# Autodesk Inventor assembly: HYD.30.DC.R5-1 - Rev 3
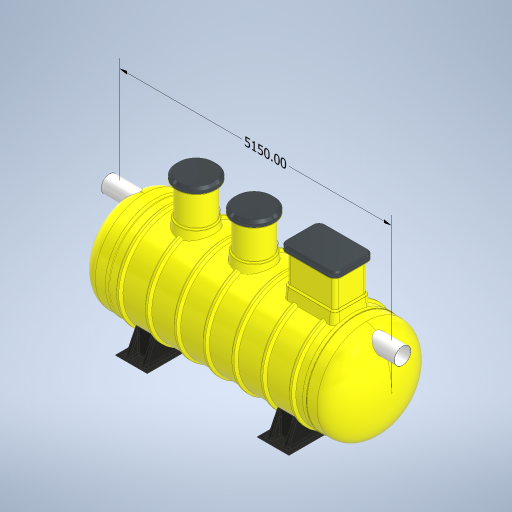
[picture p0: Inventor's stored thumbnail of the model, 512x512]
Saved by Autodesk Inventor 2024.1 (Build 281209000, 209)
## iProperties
Created: 2023-08
Part Number: HYD.30.DC.R5-1 - Rev 3
Document SubType Name: Assembly
Designer: macga
Author: macga
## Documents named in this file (43)
- D:\$ Protector Vault\Workspace\Automation Files\1. Protector Stardard Products\HydroProtectors\FAMILY\HYD.30 - Vernon\HYD.30.DC.R5-1 - Rev 3.iam
- D:\$ Protector Vault\Workspace\1. Protector Stardard Products\HydroProtectors\FAMILY\HORIZONTAL TANK - IPART\HORIZONTAL TANK - IPART.ipt
- D:\$ Protector Vault\Workspace\1. Protector Stardard Products\HydroProtectors\FAMILY\DOME - IPART\DOME - IPART\SU.DOME.1850-9.ipt
- D:\$ Protector Vault\Workspace\1. Protector Stardard Products\HydroProtectors\FAMILY\DOME - IPART\DOME - IPART.ipt
- D:\$ Protector Vault\Workspace\1. Protector Stardard Products\HydroProtectors\FAMILY\FOOT - IPART\FRP Foot - IPART\SU.HS.FOOT.1850.ipt
- D:\$ Protector Vault\Workspace\1. Protector Stardard Products\HydroProtectors\FAMILY\FOOT - IPART\FRP Foot - IPART.ipt
- D:\$ Protector Vault\Workspace\1. Protector Stardard Products\HydroProtectors\FAMILY\HYD.BAFFLE - IPART\SU.BAFFLE.1850\SU.BAFFLE.1850.ipt
- D:\$ Protector Vault\Workspace\1. Protector Stardard Products\HydroProtectors\FAMILY\HYD.BAFFLE - IPART\SU.BAFFLE.1850.ipt
- D:\$ Protector Vault\Workspace\1. Protector Stardard Products\HydroProtectors\FAMILY\ACD Base - IPART\SU.ACDBASE.1850\SU.ACDBASE.1850-300ACDFV.ipt
- D:\$ Protector Vault\Workspace\1. Protector Stardard Products\HydroProtectors\FAMILY\ACD Base - IPART\SU.ACDBASE.1850.ipt
- D:\$ Protector Vault\Workspace\1. Protector Stardard Products\HydroProtectors\FAMILY\ACDTUBE - IPART\ACDTUBE - IPART\ACDTUBE.300-1880.ipt
- D:\$ Protector Vault\Workspace\1. Protector Stardard Products\HydroProtectors\FAMILY\ACDTUBE - IPART\ACDTUBE - IPART.ipt
- D:\$ Protector Vault\Workspace\1. Protector Stardard Products\HydroProtectors\FAMILY\ACD FLOAT VALVE - IPART\ACD.FloatValve - IASSY\ACD.FVALVE.300.ASSY.iam
- D:\$ Protector Vault\Workspace\1. Protector Stardard Products\HydroProtectors\FAMILY\ACD FLOAT VALVE - IPART\ACD.FloatValve - IASSY.iam
- D:\$ Protector Vault\Workspace\1. Protector Stardard Products\HydroProtectors\FAMILY\SU.600Dia Manway Adaptor - IPART\Horizontal 600mmDia Manway Adaptor (FLANGED) SU.MWA.HS.6R-1850-1850\SU.MWA.HS.6R-1850.ipt
- D:\$ Protector Vault\Workspace\1. Protector Stardard Products\HydroProtectors\FAMILY\SU.600Dia Manway Adaptor - IPART\SU.MWA.HS.6R - IPART.ipt
- D:\$ Protector Vault\Workspace\1. Protector Stardard Products\HydroProtectors\FAMILY\WIN.600mmDiaManwayRiser - IPART\600mmDia Manway Riser.ipt
- D:\$ Protector Vault\Workspace\1. Protector Stardard Products\HydroProtectors\Automation Files\600mmDia Manway Cover.ipt
- D:\$ Protector Vault\Workspace\1. Protector Stardard Products\HydroProtectors\HYD.50 300 Outlet Vertical.ipt
- D:\$ Protector Vault\Workspace\1. Protector Stardard Products\HydroProtectors\FAMILY\OUTLET ELBOW - IPART\OUTLET ELBOW - IPART.ipt
- D:\$ Protector Vault\Workspace\1. Protector Stardard Products\HydroProtectors\Coalescer Guide Rail.ipt
- D:\$ Protector Vault\Workspace\1. Protector Stardard Products\HydroProtectors\ISO 4065 Pipe DN315x2.5xS63 - 1365.ipt
- D:\$ Protector Vault\Workspace\1. Protector Stardard Products\HydroProtectors\FAMILY\INLET PIPE ELBOW- IPART\INLET PIPE ELBOW- IPART\InletPipeElbow.300D.ipt
- D:\$ Protector Vault\Workspace\1. Protector Stardard Products\HydroProtectors\FAMILY\INLET PIPE ELBOW- IPART\INLET PIPE ELBOW- IPART.ipt
- D:\$ Protector Vault\Workspace\1. Protector Stardard Products\HydroProtectors\Upper Guide Rai Braket.ipt
- D:\$ Protector Vault\Workspace\1. Protector Stardard Products\Standard Components\Flanged Vent.ipt
- D:\$ Protector Vault\Workspace\1. Protector Stardard Products\HydroProtectors\HYD Oil Probe\Oil Probe Assembly.iam
- D:\$ Protector Vault\Workspace\1. Protector Stardard Products\Xtremeprotector\Vault\Chain.ipt
- D:\$ Protector Vault\Workspace\1. Protector Stardard Products\Xtremeprotector\Vault\Lifting Eye.ipt
- D:\$ Protector Vault\Workspace\1. Protector Stardard Products\HydroProtectors\FAMILY\OUTLET ELBOW - IPART\OUTLET ELBOW - IPART\OutletPipeElbow.300D-100DCoupling.ipt
- D:\$ Protector Vault\Workspace\1. Protector Stardard Products\HydroProtectors\FAMILY\WIN.600mmDiaManwayRiser - IPART\600mmDia Manway Riser\SU.600mmDia.ManwayRiser.600-10.ipt
- D:\$ Protector Vault\Workspace\1. Protector Stardard Products\HydroProtectors\FAMILY\Coalescer Guide Rail-014.ipt
- D:\$ Protector Vault\Workspace\Automation Files\1. Protector Stardard Products\HydroProtectors\FAMILY\CF.BASE - IPART\CF BASE SINGLE - IPART\SU.CFBASE1.1850.ipt
- D:\$ Protector Vault\Workspace\1. Protector Stardard Products\HydroProtectors\FAMILY\COALESCER FILTER - IPART\CF-R5.iam
- D:\$ Protector Vault\Workspace\1. Protector Stardard Products\Xtremeprotector\Vault\Chain\Chain-33.ipt
- D:\$ Protector Vault\Workspace\Automation Files\1. Protector Stardard Products\HydroProtectors\FAMILY\CF.BASE - IPART\CF BASE SINGLE - IPART\SU.CFBASE1.1850\SU.CFBASE1.1850.SINGLE-R5.300-OP.ipt
- D:\$ Protector Vault\Workspace\1. Protector Stardard Products\HydroProtectors\FAMILY\HORIZONTAL TANK - IPART\HORIZONTAL TANK - IPART\WIN.HB.1850x3800L-9.ipt
- D:\$ Protector Vault\Workspace\1. Protector Stardard Products\Trade Waste Sampling Point Assembly 300.iam
- D:\$ Protector Vault\Workspace\1. Protector Stardard Products\HydroProtectors\FAMILY\600x900mm Manway Adaptor - IPART\600x900mm Manway Adaptor - IPART\SU.MRADAPTOR.1850.600Lx900W.ipt
- D:\$ Protector Vault\Workspace\1. Protector Stardard Products\HydroProtectors\FAMILY\600x900mm Manway Adaptor - IPART\600x900mm Manway Adaptor - IPART.ipt
- D:\$ Protector Vault\Workspace\1. Protector Stardard Products\Standard Components\600x900 - 600mm Manway Riser.ipt
- D:\$ Protector Vault\Workspace\1. Protector Stardard Products\Standard Components\600x900mm Manway Cover ST B and D\600x900mm Manway Cover-D.ipt
- D:\$ Protector Vault\Workspace\1. Protector Stardard Products\Standard Components\600x900mm Manway Cover ST B and D.ipt
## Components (34 placed, 26 different names)
1. WIN.HB.1850x3800L-9:1
2. SU.DOME.1850-9:1 — Mate:1, Mate:3, Mate:10, Mate:88, Angle:8, Angle:9
3. SU.DOME.1850-9:2 — Mate:2, Mate:4, Angle:4, Angle:9
4. SU.HS.FOOT.1850:1 — Mate:5, Mate:6
5. SU.HS.FOOT.1850:2 — Mate:7, Mate:8
6. SU.BAFFLE.1850:1 — Mate:9, Mate:10, Mate:12
7. SU.ACDBASE.1850-300ACDFV:1 — Mate:11, Mate:12, Mate:13, Mate:14
8. ACDTUBE.300-1880:1 — Mate:13, Mate:14, Mate:15, Mate:38
9. ACD.FVALVE.300.ASSY:1 [sub-assembly] — Mate:15
10. SU.CFBASE1.1850.SINGLE-R5.300-OP:1
11. CF-R5:1 [sub-assembly] — Mate:18, Mate:19, Mate:76, Tangent:4, Tangent:6
12. SU.600mmDia.ManwayRiser.600-10:1 — Mate:30, Mate:31, Mate:40, Mate:41, Flush:2
13. 600mmDia Manway Cover:2 — Mate:30, Mate:31, Angle:2
14. HYD.50 300 Outlet Vertical:1 — Mate:34, Mate:35, Mate:36, Mate:37
15. OutletPipeElbow.300D-100DCoupling:2 — Mate:36, Mate:37, Mate:53, Mate:54, Angle:4
16. SU.MWA.HS.6R-1850:2
17. Coalescer Guide Rail-014:1 — Mate:47, Mate:62, Mate:63, Flush:5, Mate:83, Mate:84, Tangent:6
18. ISO 4065 Pipe DN315x2.5xS63 - 1365:2 — Mate:88
19. ISO 4065 Pipe DN315x2.5xS63 - 1365:1 — Mate:53, Mate:54, Mate:100, Mate:101
20. InletPipeElbow.300D:1
21. 600x900 - 600mm Manway Riser:1 — Flush:2, Mate:61, Flush:4, Mate:79, Mate:85, Mate:86, Flush:13
22. 600x900mm Manway Cover-D:1 — Mate:61, Flush:4, Angle:1, Flush:13
23. Upper Guide Rai Braket:1 — Mate:62, Mate:63, Flush:5
24. Flanged Vent:2 — Mate:68, Mate:69
25. Flanged Vent:3
26. SU.MRADAPTOR.1850.600Lx900W:1 — Flush:7
27. Oil Probe Assembly:1 [sub-assembly] — Mate:87, Flush:12, Angle:5
28. Chain-33:4 — Mate:76, Tangent:4, Tangent:5, Mate:91
29. Lifting Eye:1 — Mate:79, Mate:85, Mate:86, Tangent:5, Mate:91
30. SU.600mmDia.ManwayRiser.600-10:2
31. 600mmDia Manway Cover:3
32. SU.MWA.HS.6R-1850:3 — Mate:98, Mate:99, Mate:87
33. Flanged Vent:4
34. Trade Waste Sampling Point Assembly 300:1 [sub-assembly] — Mate:100, Mate:101
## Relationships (62: Mate 47, Flush 6, Angle 6, Tangent 3)
- Mate:1: SU.DOME.1850-9:1
- Mate:2: SU.DOME.1850-9:2
- Mate:3: SU.DOME.1850-9:1
- Mate:4: SU.DOME.1850-9:2
- Mate:5: SU.HS.FOOT.1850:1
- Mate:6: SU.HS.FOOT.1850:1
- Mate:7: SU.HS.FOOT.1850:2
- Mate:8: SU.HS.FOOT.1850:2
- Mate:9: SU.BAFFLE.1850:1
- Mate:10: SU.DOME.1850-9:1 ↔ SU.BAFFLE.1850:1
- Mate:11: SU.ACDBASE.1850-300ACDFV:1
- Mate:12: SU.BAFFLE.1850:1 ↔ SU.ACDBASE.1850-300ACDFV:1
- Mate:13: SU.ACDBASE.1850-300ACDFV:1 ↔ ACDTUBE.300-1880:1
- Mate:14: SU.ACDBASE.1850-300ACDFV:1 ↔ ACDTUBE.300-1880:1
- Mate:15: ACDTUBE.300-1880:1 ↔ ACD.FVALVE.300.ASSY:1
- Mate:18: CF-R5:1
- Mate:19: CF-R5:1
- Mate:30: SU.600mmDia.ManwayRiser.600-10:1 ↔ 600mmDia Manway Cover:2
- Mate:31: SU.600mmDia.ManwayRiser.600-10:1 ↔ 600mmDia Manway Cover:2
- Mate:34: HYD.50 300 Outlet Vertical:1
- Mate:35: HYD.50 300 Outlet Vertical:1
- Mate:36: HYD.50 300 Outlet Vertical:1 ↔ OutletPipeElbow.300D-100DCoupling:2
- Mate:37: HYD.50 300 Outlet Vertical:1 ↔ OutletPipeElbow.300D-100DCoupling:2
- Mate:38: ACDTUBE.300-1880:1
- Mate:40: SU.600mmDia.ManwayRiser.600-10:1
- Mate:41: SU.600mmDia.ManwayRiser.600-10:1
- Mate:47: Coalescer Guide Rail-014:1
- Mate:53: OutletPipeElbow.300D-100DCoupling:2 ↔ ISO 4065 Pipe DN315x2.5xS63 - 1365:1
- Mate:54: OutletPipeElbow.300D-100DCoupling:2 ↔ ISO 4065 Pipe DN315x2.5xS63 - 1365:1
- Flush:2: SU.600mmDia.ManwayRiser.600-10:1 ↔ 600x900 - 600mm Manway Riser:1
- Mate:61: 600x900 - 600mm Manway Riser:1 ↔ 600x900mm Manway Cover-D:1
- Flush:4: 600x900 - 600mm Manway Riser:1 ↔ 600x900mm Manway Cover-D:1
- Mate:62: Coalescer Guide Rail-014:1 ↔ Upper Guide Rai Braket:1
- Mate:63: Coalescer Guide Rail-014:1 ↔ Upper Guide Rai Braket:1
- Flush:5: Coalescer Guide Rail-014:1 ↔ Upper Guide Rai Braket:1
- Mate:68: Flanged Vent:2
- Mate:69: Flanged Vent:2
- Flush:7: SU.MRADAPTOR.1850.600Lx900W:1
- Angle:1: 600x900mm Manway Cover-D:1
- Angle:2: 600mmDia Manway Cover:2
- Mate:76: CF-R5:1 ↔ Chain-33:4
- Mate:79: 600x900 - 600mm Manway Riser:1 ↔ Lifting Eye:1
- Angle:4: SU.DOME.1850-9:2 ↔ OutletPipeElbow.300D-100DCoupling:2
- Mate:83: Coalescer Guide Rail-014:1
- Mate:84: Coalescer Guide Rail-014:1
- Tangent:4: CF-R5:1 ↔ Chain-33:4
- Mate:85: 600x900 - 600mm Manway Riser:1 ↔ Lifting Eye:1
- Mate:86: 600x900 - 600mm Manway Riser:1 ↔ Lifting Eye:1
- Tangent:5: Chain-33:4 ↔ Lifting Eye:1
- Mate:87: Oil Probe Assembly:1 ↔ SU.MWA.HS.6R-1850:3
- Flush:12: Oil Probe Assembly:1
- Angle:5: Oil Probe Assembly:1
- Mate:88: SU.DOME.1850-9:1 ↔ ISO 4065 Pipe DN315x2.5xS63 - 1365:2
- Flush:13: 600x900 - 600mm Manway Riser:1 ↔ 600x900mm Manway Cover-D:1
- Tangent:6: CF-R5:1 ↔ Coalescer Guide Rail-014:1
- Mate:91: Chain-33:4 ↔ Lifting Eye:1
- Angle:8: SU.DOME.1850-9:1
- Angle:9: SU.DOME.1850-9:1 ↔ SU.DOME.1850-9:2
- Mate:98: SU.MWA.HS.6R-1850:3
- Mate:99: SU.MWA.HS.6R-1850:3
- Mate:100: ISO 4065 Pipe DN315x2.5xS63 - 1365:1 ↔ Trade Waste Sampling Point Assembly 300:1
- Mate:101: ISO 4065 Pipe DN315x2.5xS63 - 1365:1 ↔ Trade Waste Sampling Point Assembly 300:1
## Named parameters: d179_d36 = 0, d180_d37 = 0, d181_d46 = 0, d182_d47 = 0, d183_d86 = 0, d184_d87 = 0
